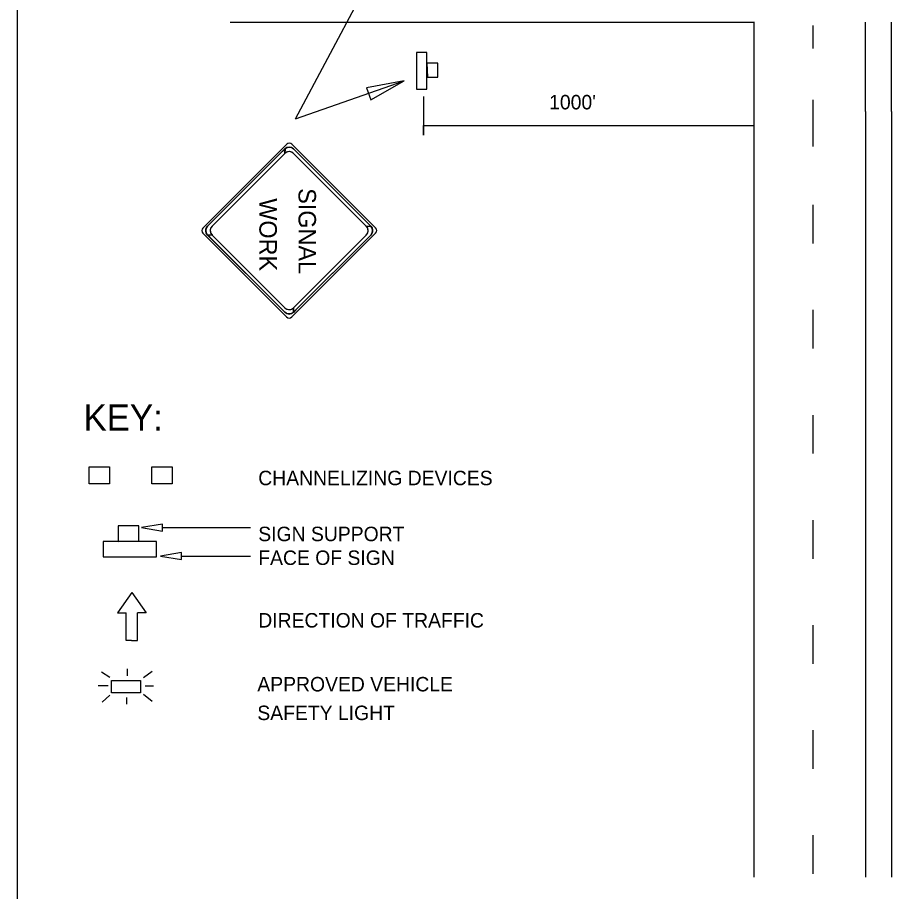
# Model space of a CAD drawing. Extents: x 1531.2 to 1538.6, y 1529.6 to 1539.9.
# Drawn here: x 1531.212 to 1534.837, y 1531.858 to 1535.482 of the extents above; entities that cross this region are included whole.
import ezdxf

# ---------------------------------------------------------------- set-up
doc = ezdxf.new("R2010")
doc.units = 0
for name, color, linetype in [('BORD-LINE', 7, 'Continuous'), ('DETL-DIMS', 7, 'Continuous'), ('DETL-LINE', 7, 'Continuous'), ('DETL-NOTE', 7, 'Continuous'), ('DETL-TITL', 7, 'Continuous'), ('USER-BORD', 7, 'Continuous')]:
    doc.layers.add(name, color=color, linetype=linetype)

# ---------------------------------------------------------------- blocks, each defined once
blk = doc.blocks.new('DIR2')
at = {"layer": 'USER-BORD'}
for p, q in [((0, 0.0012), (-0.0342, -0.0477)), ((0, 0.0012), (0.0342, -0.0477)), ((-0.0342, -0.0477), (-0.0132, -0.0477)), ((-0.0132, -0.1133), (-0.0132, -0.0477)), ((0.0342, -0.0477), (0.0132, -0.0477)), ((0.0132, -0.1133), (0.0132, -0.0477)), ((-0.0011, -0.1133), (-0.0132, -0.1133)), ((-0.0011, -0.1133), (0.0011, -0.1133)), ((0.0011, -0.1133), (0.0132, -0.1133))]:
    blk.add_line(p, q, dxfattribs=at)
blk = doc.blocks.new('SIGN13')
at = {"layer": 'USER-BORD'}
for points in [[(-0.0134, 0.0182), (0.011, 0.0189), (0.011, 0.0371), (-0.0134, 0.0371)], [(-0.0314, 0.0182), (-0.0314, 0), (0.032, 0), (0.032, 0.0182)]]:
    blk.add_lwpolyline(points, close=True, dxfattribs=at)
blk = doc.blocks.new('BAR')
at = {"layer": 'USER-BORD'}
for p, q in [((-0.011, 0.0696), (-0.0512, 0.1025)), ((0.0695, 0.1172), (0.0695, 0.0842)), ((0.15, 0.0732), (0.1866, 0.1062)), ((0.0037, 0.0037), (0.0037, 0.0622)), ((0.0037, 0.0622), (0.1427, 0.0622)), ((0.1427, 0.0622), (0.1427, 0.0037)), ((-0.0183, 0.0293), (-0.0585, 0.0293)), ((0.1427, 0.0037), (0.0037, 0.0037)), ((0.1573, 0.0293), (0.2049, 0.0293)), ((-0.011, -0.011), (-0.0512, -0.0403)), ((0.0658, -0.0183), (0.0658, -0.0513)), ((0.15, -0.011), (0.1902, -0.0366))]:
    blk.add_line(p, q, dxfattribs=at)

msp = doc.modelspace()

# ---------------------------------------------------------------- linework, layer by layer
at = {"layer": 'BORD-LINE'}
msp.add_line((1531.2124, 1531.0427), (1531.2124, 1539.9414), dxfattribs=at)
at = {"layer": 'DETL-DIMS'}
for p, q in [((1532.3661, 1535.0612), (1532.8297, 1535.9347)), ((1532.3661, 1535.0612), (1532.8163, 1535.2191)), ((1532.8962, 1535.1539), (1532.8962, 1534.9938)), ((1532.8962, 1534.9938), (1532.8962, 1535.0345)), ((1532.8962, 1535.0345), (1534.2683, 1535.0345)), ((1531.8142, 1533.3668), (1532.1793, 1533.3668)), ((1531.8922, 1533.2488), (1532.1793, 1533.2488))]:
    msp.add_line(p, q, dxfattribs=at)
for points in [[(1532.6601, 1535.1898), (1532.678, 1535.1408), (1532.8163, 1535.2191)], [(1531.8142, 1533.3523), (1531.8142, 1533.3813), (1531.7271, 1533.3668)], [(1531.8922, 1533.2343), (1531.8922, 1533.2633), (1531.805, 1533.2488)]]:
    msp.add_lwpolyline(points, close=True, dxfattribs=at)
at = {"layer": 'DETL-LINE'}
for p, q in [((1534.2683, 1535.4613), (1532.0947, 1535.4613)), ((1534.2683, 1535.092), (1534.2683, 1535.4633)), ((1534.5124, 1535.3527), (1534.5124, 1535.4485)), ((1534.7292, 1535.092), (1534.7292, 1535.4627)), ((1534.8373, 1535.092), (1534.8373, 1535.4627)), ((1534.5124, 1534.9801), (1534.5124, 1535.1401)), ((1534.2683, 1531.9169), (1534.2683, 1535.092)), ((1534.5124, 1534.9463), (1534.5124, 1535.1063)), ((1534.7292, 1535.092), (1534.7292, 1531.9169)), ((1534.8373, 1535.092), (1534.8373, 1531.9169)), ((1532.3292, 1534.9565), (1531.9813, 1534.6086)), ((1532.0008, 1534.6168), (1532.3208, 1534.9367)), ((1532.6979, 1534.6094), (1532.3508, 1534.9565)), ((1532.3576, 1534.9367), (1532.6776, 1534.6168)), ((1532.3207, 1534.9183), (1532.0192, 1534.6168)), ((1532.6591, 1534.6168), (1532.3576, 1534.9183)), ((1534.5124, 1534.5445), (1534.5124, 1534.7045)), ((1531.9813, 1534.5871), (1532.3284, 1534.24)), ((1532.3208, 1534.26), (1532.0008, 1534.5799)), ((1532.0192, 1534.5799), (1532.3207, 1534.2784)), ((1532.35, 1534.24), (1532.6979, 1534.5879)), ((1532.6776, 1534.5799), (1532.3576, 1534.26)), ((1532.3576, 1534.2784), (1532.6591, 1534.5799)), ((1534.5124, 1534.1089), (1534.5124, 1534.269)), ((1534.5124, 1533.6734), (1534.5124, 1533.8334)), ((1534.5124, 1533.2378), (1534.5124, 1533.3979)), ((1534.5124, 1532.8023), (1534.5124, 1532.9623)), ((1534.5124, 1532.3667), (1534.5124, 1532.5267)), ((1534.5124, 1531.9311), (1534.5124, 1532.0912))]:
    msp.add_line(p, q, dxfattribs=at)
for points in [[(1532.0008, 1534.6168), (1532.3116, 1534.9274), (1532.3219, 1534.9378), (1532.3207, 1534.9183), (1532.0192, 1534.6168), (1532.0145, 1534.6103), (1532.0117, 1534.6007), (1532.0125, 1534.5918), (1532.0149, 1534.5857), (1532.0192, 1534.5799), (1532.0008, 1534.5799), (1531.9956, 1534.5874), (1531.9932, 1534.5974), (1531.994, 1534.6047), (1531.9963, 1534.6108)], [(1532.3576, 1534.9367), (1532.6683, 1534.626), (1532.6786, 1534.6156), (1532.6591, 1534.6168), (1532.3576, 1534.9183), (1532.3511, 1534.923), (1532.3415, 1534.9258), (1532.3326, 1534.9251), (1532.3266, 1534.9227), (1532.3207, 1534.9183), (1532.3207, 1534.9367), (1532.3282, 1534.9419), (1532.3382, 1534.9443), (1532.3456, 1534.9435), (1532.3516, 1534.9412)], [(1532.6775, 1534.5799), (1532.3668, 1534.2692), (1532.3565, 1534.2589), (1532.3576, 1534.2784), (1532.6591, 1534.5799), (1532.6638, 1534.5864), (1532.6666, 1534.596), (1532.6659, 1534.6049), (1532.6635, 1534.6109), (1532.6591, 1534.6168), (1532.6775, 1534.6168), (1532.6828, 1534.6093), (1532.6852, 1534.5993), (1532.6844, 1534.5919), (1532.682, 1534.5859)], [(1532.3207, 1534.26), (1532.0101, 1534.5707), (1531.9997, 1534.5811), (1532.0192, 1534.5799), (1532.3207, 1534.2784), (1532.3272, 1534.2737), (1532.3368, 1534.2709), (1532.3457, 1534.2716), (1532.3518, 1534.274), (1532.3576, 1534.2784), (1532.3576, 1534.26), (1532.3501, 1534.2548), (1532.3401, 1534.2524), (1532.3328, 1534.2531), (1532.3267, 1534.2555)], [(1531.5101, 1533.5479), (1531.5101, 1533.6181), (1531.5936, 1533.6181), (1531.5936, 1533.5479)], [(1531.7701, 1533.5479), (1531.7701, 1533.6181), (1531.8537, 1533.6181), (1531.8537, 1533.5479)]]:
    msp.add_lwpolyline(points, close=True, dxfattribs=at)
for centre, radius, start, end in [((1532.3392, 1534.9183), 0.0261, 45, 135), ((1532.34, 1534.9458), 0.0152, 45, 135), ((1532.3392, 1534.8998), 0.0261, 45, 135), ((1531.9921, 1534.5979), 0.0152, 135, 225), ((1532.0193, 1534.5983), 0.0261, 135, 225), ((1532.0377, 1534.5984), 0.0261, 135, 225), ((1532.6407, 1534.5983), 0.0261, 315, 45), ((1532.6591, 1534.5983), 0.0261, 315, 45), ((1532.6871, 1534.5987), 0.0152, 315, 45), ((1532.3392, 1534.2969), 0.0261, 225, 315), ((1532.3392, 1534.2784), 0.0261, 225, 315), ((1532.3392, 1534.2508), 0.0152, 225, 315)]:
    msp.add_arc(centre, radius, start, end, dxfattribs=at)

# ---------------------------------------------------------------- block references
for name, p, xscale, yscale, rotation in [('SIGN13', (1532.867, 1535.2609), 2.391312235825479, 2.391312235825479, -90.00000000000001), ('BAR', (1531.7261, 1532.7362), 0.8711186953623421, 0.871118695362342, 180)]:
    msp.add_blockref(name, p, dxfattribs=dict(at, xscale=xscale, yscale=yscale, rotation=rotation))
for name, p, xscale, yscale in [('SIGN13', (1531.6772, 1533.2454), 3.4844747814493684, 3.484474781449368), ('DIR2', (1531.6866, 1533.0962), 1.7422373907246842, 1.742237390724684)]:
    msp.add_blockref(name, p, dxfattribs=dict(at, xscale=xscale, yscale=yscale))

# ---------------------------------------------------------------- texts
for s, p in [('SIGNAL', (1532.3779, 1534.7739)), ('WORK', (1532.2156, 1534.7321))]:
    msp.add_text(s, height=0.07256, rotation=270, dxfattribs=at).set_placement(p)
at = {"layer": 'DETL-NOTE'}
for s, p in [("1000'", (1533.4174, 1535.1007)), ('CHANNELIZING DEVICES', (1532.211, 1533.5425)), ('SIGN SUPPORT', (1532.211, 1533.3105)), ('FACE OF SIGN', (1532.211, 1533.2119)), ('DIRECTION OF TRAFFIC', (1532.211, 1532.9525)), ('APPROVED VEHICLE', (1532.2071, 1532.6876)), ('SAFETY LIGHT', (1532.2071, 1532.5687))]:
    msp.add_text(s, height=0.06, dxfattribs=at).set_placement(p)
at = {"layer": 'DETL-TITL'}
msp.add_text('KEY:', height=0.108, dxfattribs=at).set_placement((1531.486, 1533.7692))

doc.saveas('drawing.dxf')
